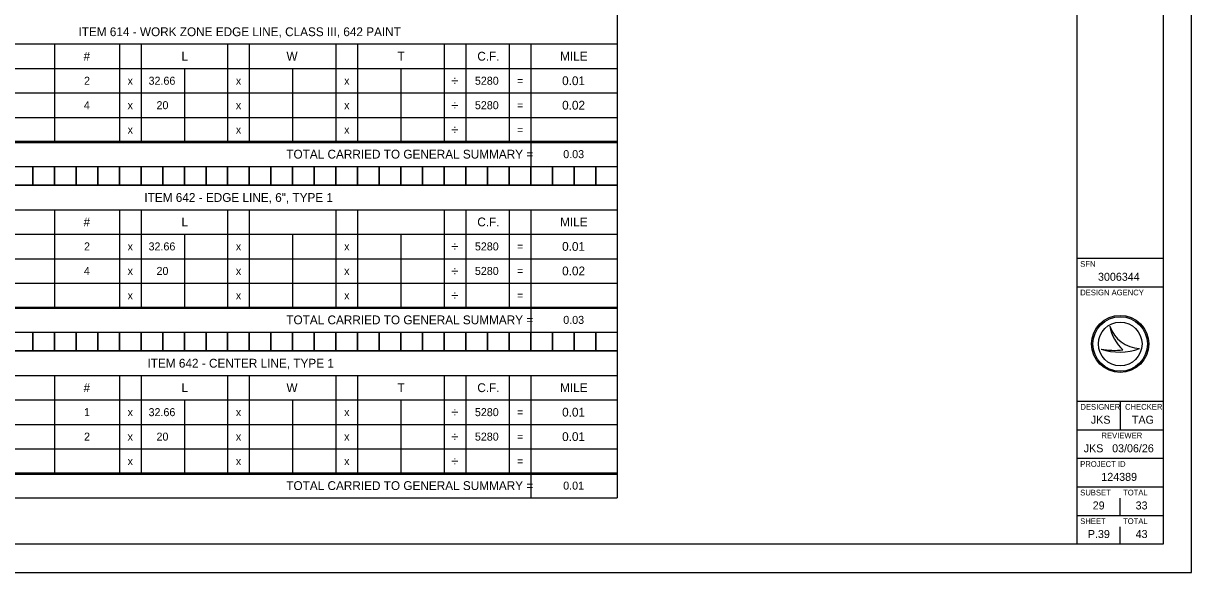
# Model space of a CAD drawing. Extents: x 0 to 34, y 0 to 22.
# Drawn here: x 13.56 to 34, y 0 to 9.61 of the extents above; entities that cross this region are included whole.
import ezdxf

# ---------------------------------------------------------------- set-up
doc = ezdxf.new("R2010")
doc.units = 0
for name, color, linetype in [('Default', 7, 'Continuous'), ('SH_Border', 7, 'Continuous'), ('SH_Cut_Line', 7, 'Continuous'), ('SH_Data', 7, 'Continuous')]:
    doc.layers.add(name, color=color, linetype=linetype)

msp = doc.modelspace()

# ---------------------------------------------------------------- linework, layer by layer
at = {"layer": 'Default'}
for p, q in [((23.951, 10.444), (23.951, 7.523)), ((10.692, 9.247), (23.951, 9.247)), ((14.102, 9.247), (14.102, 7.545)), ((15.238, 9.247), (15.238, 7.545)), ((15.617, 9.247), (15.617, 7.545)), ((17.132, 9.247), (17.132, 7.545)), ((17.511, 9.247), (17.511, 7.545)), ((19.027, 9.247), (19.027, 7.545)), ((19.405, 9.247), (19.405, 7.545)), ((20.921, 9.247), (20.921, 7.545)), ((21.299, 9.247), (21.299, 7.545)), ((22.057, 9.247), (22.057, 7.545)), ((22.436, 9.247), (22.436, 7.545)), ((10.692, 8.819), (23.951, 8.819)), ((16.375, 8.819), (16.375, 7.545)), ((18.269, 8.819), (18.269, 7.545)), ((20.163, 8.819), (20.163, 7.545)), ((10.692, 8.39), (23.951, 8.39)), ((10.692, 7.962), (23.951, 7.962)), ((10.692, 7.545), (23.951, 7.545)), ((10.692, 7.523), (23.951, 7.523)), ((22.436, 7.523), (22.436, 7.106)), ((23.951, 7.545), (23.951, 4.624)), ((10.692, 7.106), (23.951, 7.106)), ((10.692, 6.776), (23.951, 6.776)), ((10.692, 6.348), (23.951, 6.348)), ((14.102, 6.348), (14.102, 4.646)), ((15.238, 6.348), (15.238, 4.646)), ((15.617, 6.348), (15.617, 4.646)), ((17.132, 6.348), (17.132, 4.646)), ((17.511, 6.348), (17.511, 4.646)), ((19.027, 6.348), (19.027, 4.646)), ((19.405, 6.348), (19.405, 4.646)), ((20.921, 6.348), (20.921, 4.646)), ((21.299, 6.348), (21.299, 4.646)), ((22.057, 6.348), (22.057, 4.646)), ((22.436, 6.348), (22.436, 4.646)), ((10.692, 5.92), (23.951, 5.92)), ((16.375, 5.92), (16.375, 4.646)), ((18.269, 5.92), (18.269, 4.646)), ((20.163, 5.92), (20.163, 4.646)), ((10.692, 5.491), (23.951, 5.491)), ((10.692, 5.063), (23.951, 5.063)), ((10.692, 4.646), (23.951, 4.646)), ((10.692, 4.624), (23.951, 4.624)), ((22.436, 4.624), (22.436, 4.207)), ((23.951, 4.646), (23.951, 1.725)), ((10.692, 4.207), (23.951, 4.207)), ((10.692, 3.877), (23.951, 3.877)), ((10.692, 3.449), (23.951, 3.449)), ((14.102, 3.449), (14.102, 1.747)), ((15.238, 3.449), (15.238, 1.747)), ((15.617, 3.449), (15.617, 1.747)), ((17.132, 3.449), (17.132, 1.747)), ((17.511, 3.449), (17.511, 1.747)), ((19.027, 3.449), (19.027, 1.747)), ((19.405, 3.449), (19.405, 1.747)), ((20.921, 3.449), (20.921, 1.747)), ((21.299, 3.449), (21.299, 1.747)), ((22.057, 3.449), (22.057, 1.747)), ((22.436, 3.449), (22.436, 1.747)), ((10.692, 3.021), (23.951, 3.021)), ((16.375, 3.021), (16.375, 1.747)), ((18.269, 3.021), (18.269, 1.747)), ((20.163, 3.021), (20.163, 1.747)), ((10.692, 2.593), (23.951, 2.593)), ((10.692, 2.164), (23.951, 2.164)), ((10.692, 1.747), (23.951, 1.747)), ((10.692, 1.725), (23.951, 1.725)), ((22.436, 1.725), (22.436, 1.308)), ((23.951, 1.747), (23.951, 1.308)), ((10.692, 1.308), (23.951, 1.308))]:
    msp.add_line(p, q, dxfattribs=at)
for points in [[(13.344, 7.106), (13.723, 7.106), (13.723, 6.776), (13.344, 6.776)], [(13.723, 7.106), (14.102, 7.106), (14.102, 6.776), (13.723, 6.776)], [(14.102, 7.106), (14.481, 7.106), (14.481, 6.776), (14.102, 6.776)], [(14.481, 7.106), (14.859, 7.106), (14.859, 6.776), (14.481, 6.776)], [(14.859, 7.106), (15.238, 7.106), (15.238, 6.776), (14.859, 6.776)], [(15.238, 7.106), (15.617, 7.106), (15.617, 6.776), (15.238, 6.776)], [(15.617, 7.106), (15.996, 7.106), (15.996, 6.776), (15.617, 6.776)], [(15.996, 7.106), (16.375, 7.106), (16.375, 6.776), (15.996, 6.776)], [(16.375, 7.106), (16.754, 7.106), (16.754, 6.776), (16.375, 6.776)], [(16.754, 7.106), (17.132, 7.106), (17.132, 6.776), (16.754, 6.776)], [(17.132, 7.106), (17.511, 7.106), (17.511, 6.776), (17.132, 6.776)], [(17.511, 7.106), (17.89, 7.106), (17.89, 6.776), (17.511, 6.776)], [(17.89, 7.106), (18.269, 7.106), (18.269, 6.776), (17.89, 6.776)], [(18.269, 7.106), (18.648, 7.106), (18.648, 6.776), (18.269, 6.776)], [(18.648, 7.106), (19.027, 7.106), (19.027, 6.776), (18.648, 6.776)], [(19.027, 7.106), (19.405, 7.106), (19.405, 6.776), (19.027, 6.776)], [(19.405, 7.106), (19.784, 7.106), (19.784, 6.776), (19.405, 6.776)], [(19.784, 7.106), (20.163, 7.106), (20.163, 6.776), (19.784, 6.776)], [(20.163, 7.106), (20.542, 7.106), (20.542, 6.776), (20.163, 6.776)], [(20.542, 7.106), (20.921, 7.106), (20.921, 6.776), (20.542, 6.776)], [(20.921, 7.106), (21.299, 7.106), (21.299, 6.776), (20.921, 6.776)], [(21.299, 7.106), (21.678, 7.106), (21.678, 6.776), (21.299, 6.776)], [(21.678, 7.106), (22.057, 7.106), (22.057, 6.776), (21.678, 6.776)], [(22.057, 7.106), (22.436, 7.106), (22.436, 6.776), (22.057, 6.776)], [(22.436, 7.106), (22.815, 7.106), (22.815, 6.776), (22.436, 6.776)], [(22.815, 7.106), (23.194, 7.106), (23.194, 6.776), (22.815, 6.776)], [(23.194, 7.106), (23.572, 7.106), (23.572, 6.776), (23.194, 6.776)], [(23.572, 7.106), (23.951, 7.106), (23.951, 6.776), (23.572, 6.776)], [(13.344, 4.207), (13.723, 4.207), (13.723, 3.877), (13.344, 3.877)], [(13.723, 4.207), (14.102, 4.207), (14.102, 3.877), (13.723, 3.877)], [(14.102, 4.207), (14.481, 4.207), (14.481, 3.877), (14.102, 3.877)], [(14.481, 4.207), (14.859, 4.207), (14.859, 3.877), (14.481, 3.877)], [(14.859, 4.207), (15.238, 4.207), (15.238, 3.877), (14.859, 3.877)], [(15.238, 4.207), (15.617, 4.207), (15.617, 3.877), (15.238, 3.877)], [(15.617, 4.207), (15.996, 4.207), (15.996, 3.877), (15.617, 3.877)], [(15.996, 4.207), (16.375, 4.207), (16.375, 3.877), (15.996, 3.877)], [(16.375, 4.207), (16.754, 4.207), (16.754, 3.877), (16.375, 3.877)], [(16.754, 4.207), (17.132, 4.207), (17.132, 3.877), (16.754, 3.877)], [(17.132, 4.207), (17.511, 4.207), (17.511, 3.877), (17.132, 3.877)], [(17.511, 4.207), (17.89, 4.207), (17.89, 3.877), (17.511, 3.877)], [(17.89, 4.207), (18.269, 4.207), (18.269, 3.877), (17.89, 3.877)], [(18.269, 4.207), (18.648, 4.207), (18.648, 3.877), (18.269, 3.877)], [(18.648, 4.207), (19.027, 4.207), (19.027, 3.877), (18.648, 3.877)], [(19.027, 4.207), (19.405, 4.207), (19.405, 3.877), (19.027, 3.877)], [(19.405, 4.207), (19.784, 4.207), (19.784, 3.877), (19.405, 3.877)], [(19.784, 4.207), (20.163, 4.207), (20.163, 3.877), (19.784, 3.877)], [(20.163, 4.207), (20.542, 4.207), (20.542, 3.877), (20.163, 3.877)], [(20.542, 4.207), (20.921, 4.207), (20.921, 3.877), (20.542, 3.877)], [(20.921, 4.207), (21.299, 4.207), (21.299, 3.877), (20.921, 3.877)], [(21.299, 4.207), (21.678, 4.207), (21.678, 3.877), (21.299, 3.877)], [(21.678, 4.207), (22.057, 4.207), (22.057, 3.877), (21.678, 3.877)], [(22.057, 4.207), (22.436, 4.207), (22.436, 3.877), (22.057, 3.877)], [(22.436, 4.207), (22.815, 4.207), (22.815, 3.877), (22.436, 3.877)], [(22.815, 4.207), (23.194, 4.207), (23.194, 3.877), (22.815, 3.877)], [(23.194, 4.207), (23.572, 4.207), (23.572, 3.877), (23.194, 3.877)], [(23.572, 4.207), (23.951, 4.207), (23.951, 3.877), (23.572, 3.877)]]:
    msp.add_lwpolyline(points, close=True, dxfattribs=at)
at = {"layer": 'SH_Border'}
for p, q in [((32, 0.5), (32, 21.5)), ((32, 5.5), (33.5, 5.5)), ((32, 5), (33.5, 5)), ((32, 3), (33.5, 3)), ((32.75, 3), (32.75, 2.5)), ((32, 2.5), (33.5, 2.5)), ((32, 2), (33.5, 2)), ((32, 1.5), (33.5, 1.5)), ((32, 1), (33.5, 1))]:
    msp.add_line(p, q, dxfattribs=at)
msp.add_lwpolyline([(1.5, 21.5), (33.5, 21.5), (33.5, 0.5), (1.5, 0.5)], close=True, dxfattribs=at)
at = {"layer": 'SH_Cut_Line'}
msp.add_lwpolyline([(0, 0), (34, 0), (34, 22), (0, 22)], close=True, dxfattribs=at)
at = {"layer": 'SH_Data'}
for p, q in [((32.567, 4.31), (32.567, 4.31)), ((32.417, 3.91), (32.417, 3.91)), ((32.75, 4), (32.75, 4)), ((33.087, 3.919), (33.087, 3.919)), ((32.75, 1), (32.75, 1.3)), ((32.375, 0.675), (32.375, 0.675)), ((32.75, 0.5), (32.75, 0.8))]:
    msp.add_line(p, q, dxfattribs=at)
for radius in [0.5, 0.477, 0.477, 0.382]:
    msp.add_circle((32.75, 4), radius, dxfattribs=at)
for centre, radius, start, end in [((33.116, 4.498), 0.58, 198.9257, 198.9319), ((33.347, 4.47), 0.796, 191.6379, 191.6421), ((33.116, 4.498), 0.58, 198.9319, 267.1657), ((33.347, 4.47), 0.796, 191.6421, 226.0947), ((32.739, 4.87), 1.013, 251.4576, 290.0832), ((32.648, 5.154), 1.266, 259.4964, 259.4995), ((32.739, 4.87), 1.013, 251.4527, 251.4576), ((32.648, 5.154), 1.266, 259.4995, 276.6672)]:
    msp.add_arc(centre, radius, start, end, dxfattribs=at)

# ---------------------------------------------------------------- texts
at = {"layer": 'Default'}
for s, height, p in [('ITEM 614 - WORK ZONE EDGE LINE, CLASS III, 642 PAINT', 0.154, (14.522, 9.384)), ('#', 0.154, (14.611, 8.956)), ('L', 0.154, (16.324, 8.956)), ('W', 0.154, (18.162, 8.956)), ('T', 0.154, (20.104, 8.956)), ('C.F.', 0.154, (21.501, 8.956)), ('MILE', 0.154, (22.95, 8.956)), ('2', 0.14, (14.62, 8.534)), ('x', 0.14, (15.382, 8.534)), ('32.66', 0.14, (15.749, 8.534)), ('x', 0.14, (17.276, 8.534)), ('x', 0.14, (19.171, 8.534)), ('÷', 0.168, (21.048, 8.52)), ('5280', 0.14, (21.459, 8.534)), ('=', 0.14, (22.197, 8.534)), ('0.01', 0.154, (22.985, 8.527)), ('4', 0.14, (14.617, 8.106)), ('x', 0.14, (15.382, 8.106)), ('20', 0.14, (15.888, 8.106)), ('x', 0.14, (17.276, 8.106)), ('x', 0.14, (19.171, 8.106)), ('÷', 0.168, (21.048, 8.092)), ('5280', 0.14, (21.459, 8.106)), ('=', 0.14, (22.197, 8.106)), ('0.02', 0.154, (22.985, 8.099)), ('x', 0.14, (15.382, 7.678)), ('x', 0.14, (17.276, 7.678)), ('x', 0.14, (19.171, 7.678)), ('÷', 0.168, (21.048, 7.664)), ('=', 0.14, (22.197, 7.678)), ('TOTAL CARRIED TO GENERAL SUMMARY =', 0.154, (18.159, 7.243)), ('0.03', 0.14, (23.005, 7.25)), ('ITEM 642 - EDGE LINE, 6", TYPE 1', 0.154, (15.676, 6.485)), ('#', 0.154, (14.611, 6.057)), ('L', 0.154, (16.324, 6.057)), ('C.F.', 0.154, (21.501, 6.057)), ('MILE', 0.154, (22.95, 6.057)), ('2', 0.14, (14.62, 5.636)), ('x', 0.14, (15.382, 5.636)), ('32.66', 0.14, (15.749, 5.636)), ('x', 0.14, (17.276, 5.636)), ('x', 0.14, (19.171, 5.636)), ('÷', 0.168, (21.048, 5.622)), ('5280', 0.14, (21.459, 5.636)), ('=', 0.14, (22.197, 5.636)), ('0.01', 0.154, (22.985, 5.629)), ('4', 0.14, (14.617, 5.207)), ('20', 0.14, (15.888, 5.207)), ('÷', 0.168, (21.048, 5.193)), ('5280', 0.14, (21.459, 5.207)), ('0.02', 0.154, (22.985, 5.2)), ('x', 0.14, (15.382, 5.207)), ('x', 0.14, (17.276, 5.207)), ('x', 0.14, (19.171, 5.207)), ('=', 0.14, (22.197, 5.207)), ('x', 0.14, (15.382, 4.779)), ('x', 0.14, (17.276, 4.779)), ('x', 0.14, (19.171, 4.779)), ('÷', 0.168, (21.048, 4.765)), ('=', 0.14, (22.197, 4.779)), ('TOTAL CARRIED TO GENERAL SUMMARY =', 0.154, (18.159, 4.344)), ('0.03', 0.14, (23.005, 4.351)), ('ITEM 642 - CENTER LINE, TYPE 1', 0.154, (15.73, 3.586)), ('#', 0.154, (14.611, 3.158)), ('L', 0.154, (16.324, 3.158)), ('W', 0.154, (18.162, 3.158)), ('T', 0.154, (20.104, 3.158)), ('C.F.', 0.154, (21.501, 3.158)), ('MILE', 0.154, (22.95, 3.158)), ('1', 0.14, (14.62, 2.737)), ('32.66', 0.14, (15.749, 2.737)), ('5280', 0.14, (21.459, 2.737)), ('0.01', 0.154, (22.985, 2.73)), ('x', 0.14, (15.382, 2.737)), ('x', 0.14, (17.276, 2.737)), ('x', 0.14, (19.171, 2.737)), ('÷', 0.168, (21.048, 2.723)), ('=', 0.14, (22.197, 2.737)), ('0.01', 0.154, (22.985, 2.302)), ('2', 0.14, (14.62, 2.309)), ('x', 0.14, (15.382, 2.309)), ('20', 0.14, (15.888, 2.309)), ('x', 0.14, (17.276, 2.309)), ('x', 0.14, (19.171, 2.309)), ('÷', 0.168, (21.048, 2.295)), ('5280', 0.14, (21.459, 2.309)), ('=', 0.14, (22.197, 2.309)), ('x', 0.14, (15.382, 1.88)), ('x', 0.14, (17.276, 1.88)), ('x', 0.14, (19.171, 1.88)), ('÷', 0.168, (21.048, 1.866)), ('=', 0.14, (22.197, 1.88)), ('TOTAL CARRIED TO GENERAL SUMMARY =', 0.154, (18.159, 1.445)), ('0.01', 0.14, (23.004, 1.452))]:
    msp.add_text(s, height=height, dxfattribs=at).set_placement(p)
at = {"layer": 'SH_Data'}
for s, height, p in [('SFN', 0.1, (32.05, 5.35)), ('3006344', 0.14, (32.362, 5.105)), ('DESIGN AGENCY', 0.1, (32.05, 4.85)), ('DESIGNER', 0.1, (32.054, 2.85)), ('CHECKER', 0.1, (32.835, 2.85)), ('JKS', 0.14, (32.237, 2.605)), ('TAG', 0.14, (32.955, 2.605)), ('REVIEWER', 0.1, (32.422, 2.35)), ('03/06/26', 0.14, (32.609, 2.105)), ('JKS', 0.14, (32.112, 2.105)), ('PROJECT ID', 0.1, (32.05, 1.85)), ('124389', 0.14, (32.42, 1.605)), ('SUBSET', 0.1, (32.05, 1.35)), ('TOTAL', 0.1, (32.8, 1.35)), ('29', 0.14, (32.269, 1.105)), ('33', 0.14, (33.02, 1.105)), ('SHEET', 0.1, (32.05, 0.85)), ('TOTAL', 0.1, (32.8, 0.85)), ('P.39', 0.14, (32.184, 0.605)), ('43', 0.14, (33.02, 0.605))]:
    msp.add_text(s, height=height, dxfattribs=at).set_placement(p)

doc.saveas('drawing.dxf')
